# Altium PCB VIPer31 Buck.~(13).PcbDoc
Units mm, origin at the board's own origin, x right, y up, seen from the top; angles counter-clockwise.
Board outline 152.4 x 101.6 mm, 2 copper layers (Top Layer, Bottom Layer); 37 components, 16 nets, 72 pads, 0 vias.
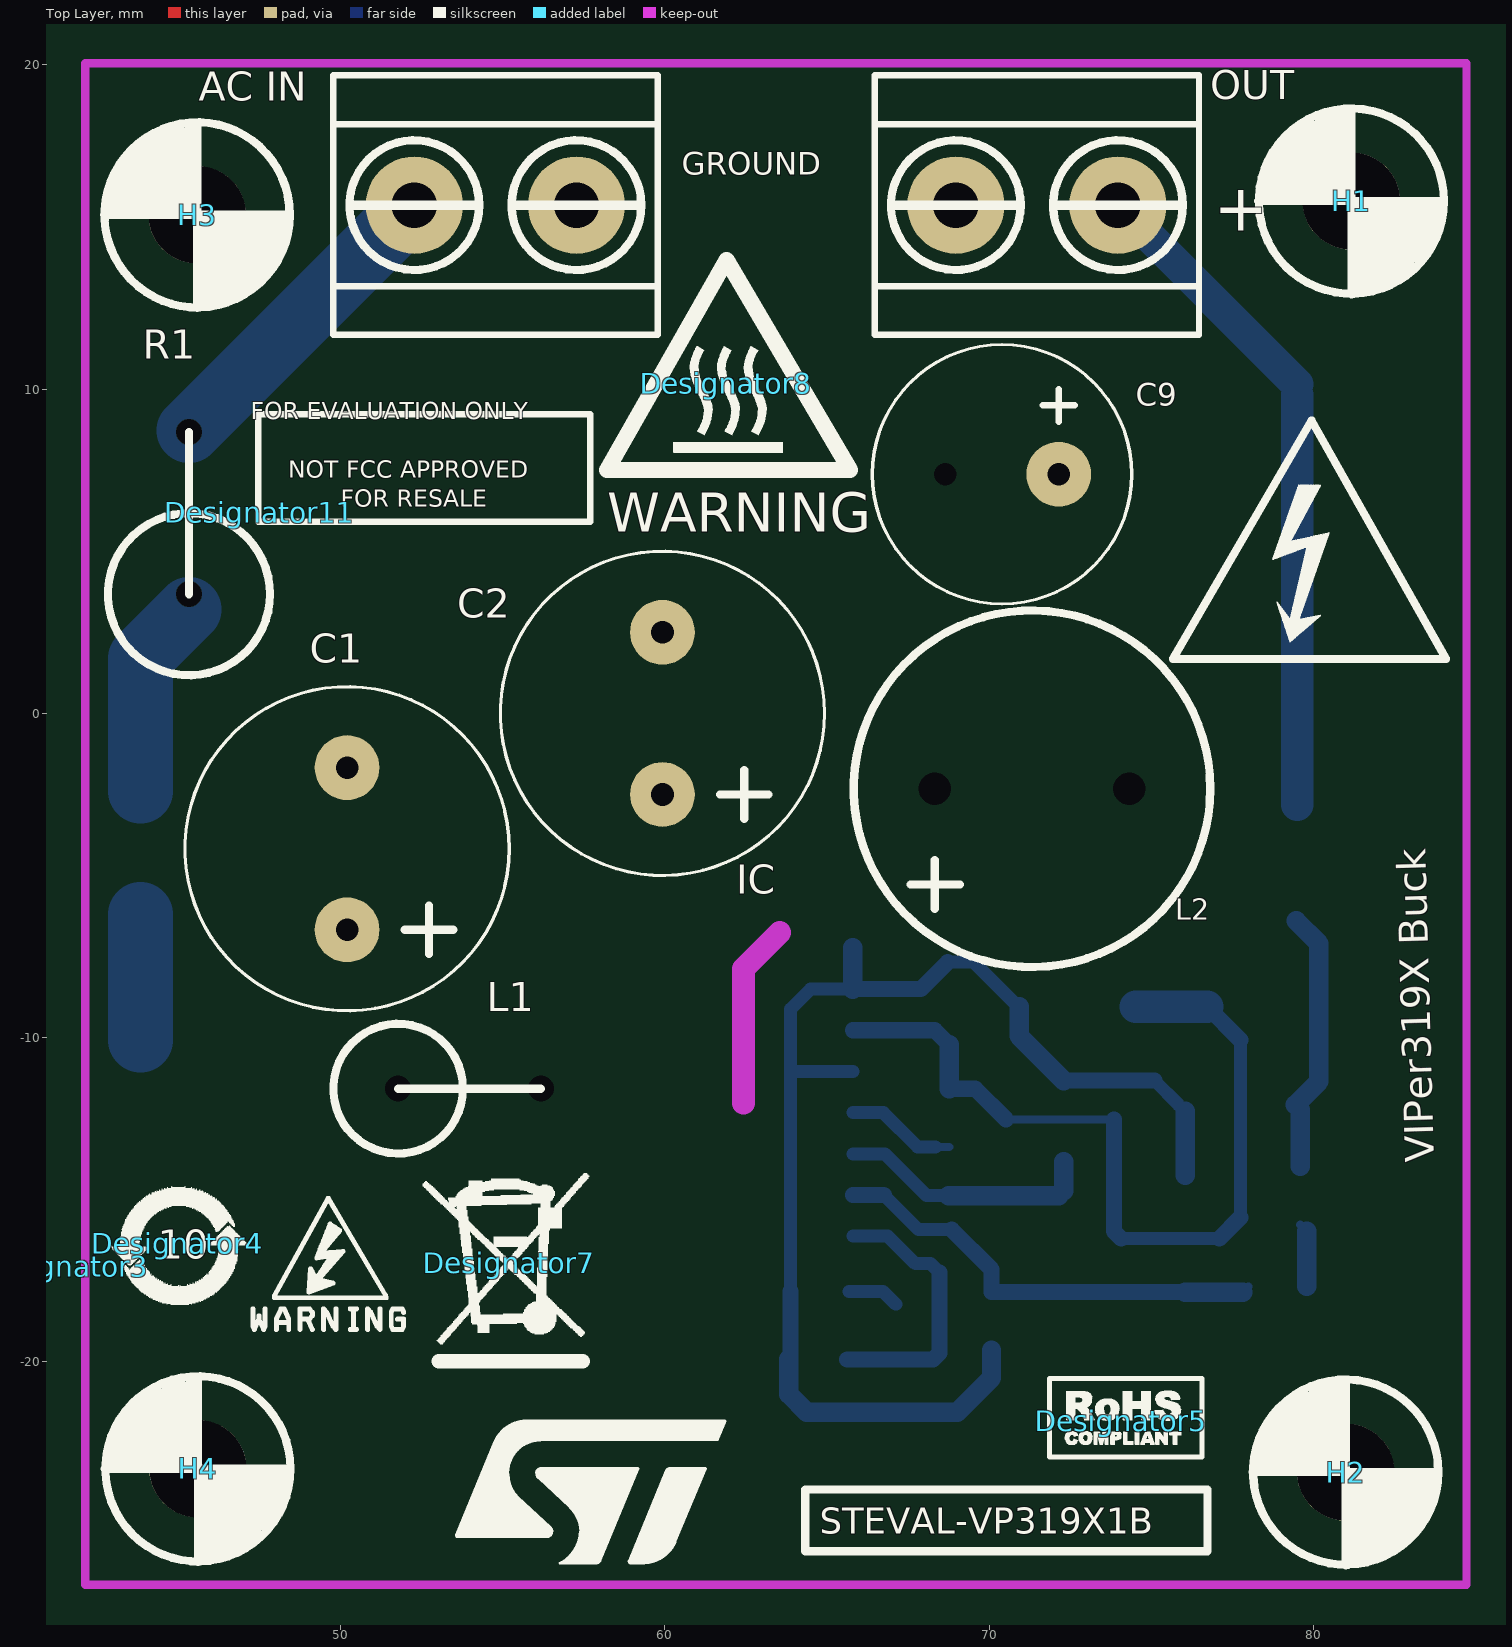
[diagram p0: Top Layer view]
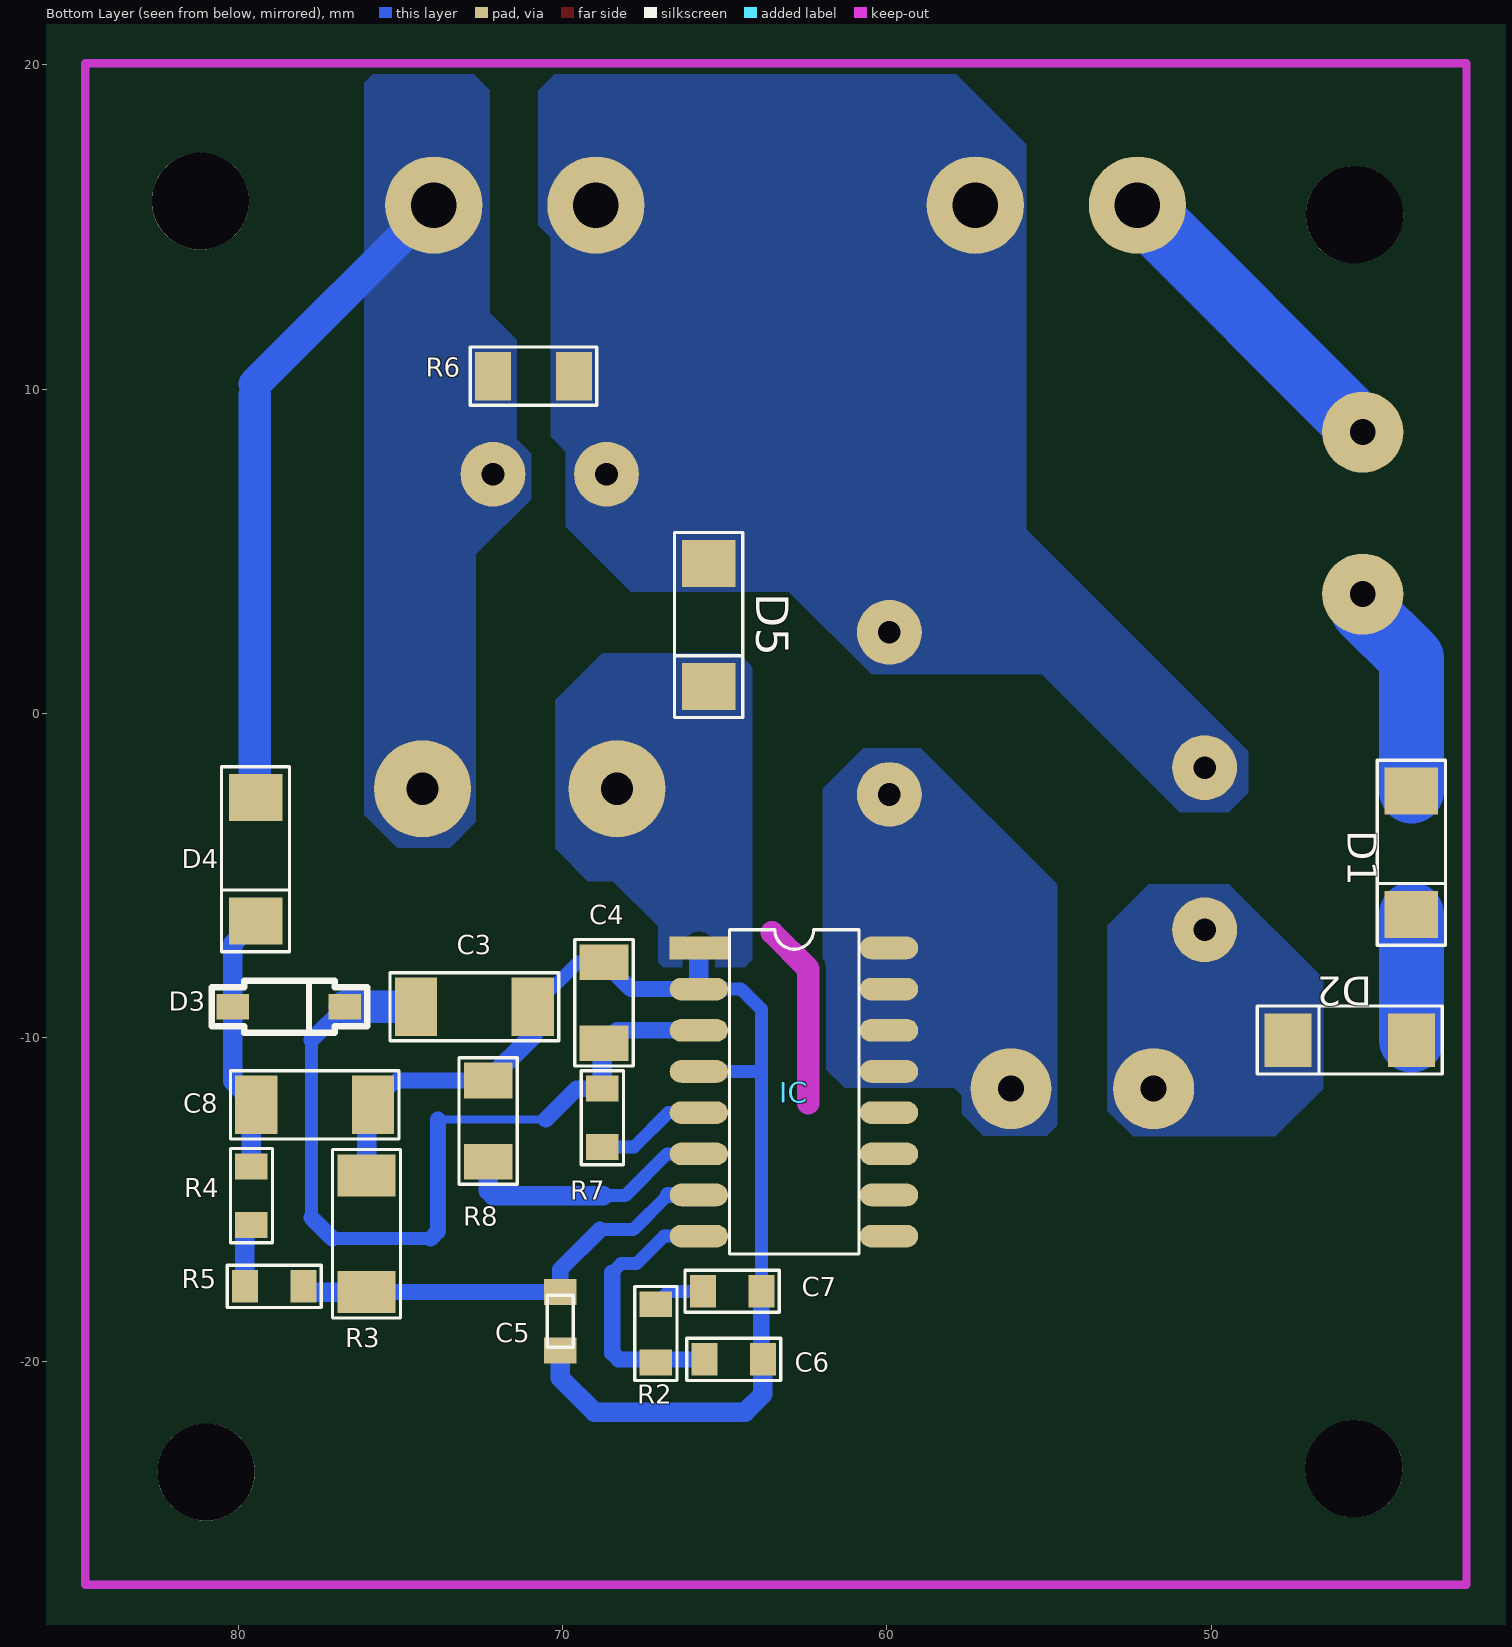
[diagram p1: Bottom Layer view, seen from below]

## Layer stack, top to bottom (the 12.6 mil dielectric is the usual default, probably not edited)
Top Solder: solder mask 0.0102, Solder Resist, Dk 3.5
Top Layer: signal copper 0.0356
Dielectric 1: dielectric 0.32, FR-4, Dk 4.8
Bottom Layer: signal copper 0.0356
Bottom Solder: solder mask 0.0102, Solder Resist, Dk 3.5

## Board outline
-0.1,-51.05 152.3,-51.05 152.3,50.55 -0.1,50.55

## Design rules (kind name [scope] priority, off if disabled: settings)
Clearance Clearance_1 [All] p1: gap=0.2 ignorepadtopadclearanceinfootprint=FALSE except(0: Arc-Hole Track-Hole SMDPad-Hole THPad-Hole Via-Hole Fill-Hole Poly-Hole Region-Hole Text-Hole)
Clearance [All] p2: gap=0.254 ignorepadtopadclearanceinfootprint=FALSE except(0: Arc-Poly Arc-Hole Track-Poly Track-Region Track-Hole SMDPad-Poly SMDPad-Hole THPad-Poly THPad-Hole Via-Poly Via-Hole Fill-Poly Fill-Hole Poly-Poly Poly-Hole Region-Hole Text-Hole)
PolygonConnect [All] p1: connectstyle=Direct reliefconductorwidth=0.254 reliefentries=4 polygonreliefangle="90 Angle" airgapwidth=0.254
RoutingVias [All] p1: holewidth=0.711 width=1.27 viastyle="Through Hole" minholewidth=0.711 minwidth=1.27 maxholewidth=0.711 maxwidth=1.27
SolderMaskExpansion [All] p1: expansion=0.102
Width [All] p1: maxlimit=2 minlimit=0.254 preferedwidth=0.254 minimp=50.000000 maximp=50.000000 favimp=50.000000
30 further rules are at their usual default settings.

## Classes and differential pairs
component class VIPer31_buck: "AC IN" C1 C2 C3 C4 C5 C6 C7 C8 C9 D1 D2 D3 D4 D5 H1 H2 H3 H4 IC L1 L2 OUT R1 R2 R3 R4 R5 R6 R7 R8 Rbl VR1

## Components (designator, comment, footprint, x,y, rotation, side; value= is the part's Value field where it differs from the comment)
"AC IN" "input connector" SM.2VITE 57.275,15.675 r180 top (schematic designator IN)
C1 "22 uF 400 Vcc" CAPOL-5X10 50.2,-6.675 r90 top value="68 uF +/-20%, 400 Vcc, +105°C"
C2 "22 uF 400 Vcc" CAPOL-5X10 59.925,-2.5 r90 top value="68 uF +/-20%, 400 Vcc, +105°C"
C3 "4.7uF 50V" R-1206-B2 74.525,-9.05 r180 top value="1 nF 630 Vdc"
C4 "100pF" R-0805-B2 68.725,-10.175 r90 top value="100 pF +/-5%, 250 Vdc"
C5 "n.c." R-0603-B 70.075,-19.65 r90 top value=100pF
C6 "tbd" R-0603-B2 65.625,-19.925 r180 top value="1 nF +/-5%, 200 Vdc"
C7 "tbd" R-0603-B2 65.675,-17.825 r180 top
C8 "220 nF" R-1206-B2 79.45,-12.075 r180 top value="100nF ±10%, 25 Vcc"
C9 "680 uF, 25 Vcc" CAPOL-3.5X8 72.15,7.375 r180 top value="470 uF +/-20%, 35 Vcc, +105°C"
D1 "MRA4007" SMA-2 43.825,-2.4 r90 top
D2 "MRA4007" SMA-2 43.825,-10.075 r180 top
D3 "BAT46ZFILM" SOD-123 80.175,-9.05 r0 top value=MRA4007T3G
D4 "STTH1L06" SMA-2 79.475,-2.6 r90 top value="1 A, 150 V"
D5 "STTH1L06" SMA-2 65.5,4.625 r90 top value="Schottky diode, 10A, 200 V"
Designator3 "Comment" High-Voltage-Logo-5mm 41.425,-17.05 r0 top
Designator4 "Comment" "RoHS-CH-Logo 10-4mm" 44.975,-16.35 r0 top
Designator5 "Comment" RoHS-EU-Logo-4.5mm 74.075,-21.825 r0 top
Designator7 "Comment" WASTE_5mm 55.2,-16.95 r0 top
Designator8 "Comment" "HOT SURFACE-logo-8mm" 61.9,10.175 r0 top
Designator11 "Comment" ADVISE_small 47.5,6.2 r0 top
H1 "HOLE" FORO 81.175,15.8 r0 top
H2 "HOLE" FORO 81,-23.4 r0 top
H3 "HOLE" FORO 45.575,15.375 r0 top
H4 "HOLE" FORO 45.6,-23.3 r0 top
IC "VIPER31_SO16" SO-16N_2 65.8,-7.235 r270 top
L1 "1mH" 1W-VER 51.775,-11.575 r0 top value="3.3UH 3.23A 33 MOHM"
L2 "270uH" CAPOL-6X11 68.325,-2.325 r0 top value="3.3UH 3.23A 33 MOHM"
OUT "output connector" SM.2VITE 73.975,15.675 r180 top
R1 "10 Ohm" 2W-VER 45.325,3.675 r90 top
R2 "tbd" R-0603-B2 67.125,-18.225 r270 top
R3 "22k" R-1206-B2 76.05,-14.25 r270 top value="0 Ohm, 0.25W"
R4 "22k" R-0603-B2 79.6,-15.775 r90 top
R5 "56k" R-0603-B2 79.8,-17.675 r180 top
R6 "5.6 kOhm" R-0805-B2 69.65,10.4 r0 top value="1MOhm +/-5%"
R7 "0" R-0603-B2 68.775,-11.575 r270 top
R8 "Res1" R-0805-B2 72.3,-11.325 r270 top value=0

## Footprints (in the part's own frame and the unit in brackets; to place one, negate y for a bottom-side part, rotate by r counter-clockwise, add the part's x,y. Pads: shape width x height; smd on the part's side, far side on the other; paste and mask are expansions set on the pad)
1W-VER [mm]
  round 0 / inner round 0 / far side round 2.5 hole 0.8: 1(0,0) 2(4.4,0)
  silkscreen extent -2,-2 4.4,2
2W-VER [mm]
  round 0 / inner round 0 / far side round 2.5 hole 0.8: 1(0,0) 2(5,0)
  silkscreen extent -2.5,-2.5 5,2.5
ADVISE_small [mm]
  silkscreen extent -0.04,-0.29 10.2,3.02
CAPOL-3.5X8 [mm]
  round 2 hole 0.7: 1(0,0)
  round 0 / inner round 0 / far side round 2 hole 0.7: 2(3.5,0)
  silkscreen extent -2.25,-4 5.75,4
CAPOL-5X10 [mm]
  round 2 hole 0.7: 1(0,0) 2(5,0)
  silkscreen extent -2.5,-5 7.5,5
CAPOL-6X11 [mm]
  round 0 / inner round 0 / far side round 3 hole 1: 1(0,0) 2(6,0)
  silkscreen extent -2.5,-5.5 8.5,5.5
FORO [mm]
  round 3 hole 3: 1(0,0)
  silkscreen extent -2.88,-2.88 2.86,2.86
High-Voltage-Logo-5mm [mm]
  silkscreen extent 5.83,-1.99 10.55,2.13
"HOT SURFACE-logo-8mm" [mm]
  silkscreen extent -3.68,-2.67 3.81,3.81
R-0603-B [mm]
  rect 0.8x1 smd far side: 1(0,0) 2(1.8,0)
R-0603-B2 [mm]
  rect 0.8x1 smd far side: 1(0,0) 2(1.8,0)
R-0805-B2 [mm]
  rect 1.1x1.5 smd far side: 1(0,0) 2(2.5,0)
R-1206-B2 [mm]
  rect 1.3x1.8 smd far side: 1(0,0) 2(3.6,0)
"RoHS-CH-Logo 10-4mm" [mm]
  silkscreen extent -2.05,-1.88 2.14,1.74
RoHS-EU-Logo-4.5mm [mm]
  silkscreen extent -2.21,-1.11 2.5,1.31
SM.2VITE [mm]
  round 3 hole 1.4: 1(0,0) 2(5,0)
  silkscreen extent -2.5,-4 7.5,4
SMA-2 [mm]
  rect 1.45x1.65 smd far side: 1(0,0) 2(-3.8,0)
SO-16N_2 [mm]
  rect 0.7x1.8 smd far side: 1(0,0)
  oval 0.7x1.8 smd far side: 2(1.27,0) 3(2.54,0) 4(3.81,0) 5(5.08,0) 6(6.35,0) 7(7.62,0) 8(8.89,0) 9(8.89,-5.864) 10(7.62,-5.864) 11(6.35,-5.864) 12(5.08,-5.864) 13(3.81,-5.864) 14(2.54,-5.864) 15(1.27,-5.864) 16(0,-5.864)
SOD-123 [mm]
  rect 1x0.8 smd far side: 1(0,0) 2(-3.45,0)
WASTE_5mm [mm]
  silkscreen extent -2.67,-3.03 2.46,2.77

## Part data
"AC IN" OUT: library part M.2VITE, "Morsetti"
C1 C2: library part "Cap Pol1", "Polarized Capacitor (Radial)", Package="TH D{}18 mm, H{}25 mm, P{}7.5 mm", Part number=400BXC68MEFC18X25
C3: library part CAP, "1 nF 630 V multi layer capacitor", Package="SMD 1206", Part number=C3216C0G2J102J085AA
C4: library part CAP, "100 pF 250 Vdc multi layer capacitor", Package="SMD 0603", Part number=CGA3E3C0G2E101J080AA
C5: library part Cap, "Capacitor"
C6: library part CAP, "1 nF 200 Vdc multi layer capacitor", Package="SMD 0603", Part number=C0603C102J2GACAUTO
C7: library part CAP, "NC", Package="SMD 0603"
C8: library part CAP, "100nF ±10%, 25 Vcc, MLCC", Package="SMD 0603", Part number=C0603C104K3RACTU
C9: library part "Cap Pol1", "470 uF +/-20%, 35 Vcc, +105°C", Package="TH D{}10 mm, H{}12.5 mm, P{}5 mm", Part number=25ZLH470MEFC10X12.5
D1 D2: library part "Diode 1N4007", "1 Amp General Purpose Rectifier"
D3: library part Diode, "Silicon Diode, 1 A, 1000 V", Part number=MRA4007T3G
D4: library part Diode, "small signal diode", Part number=STPS1150A
D5: library part Diode, "Schottky diode, 10A, 200 V", Part number=STPS2200UF
IC: "Integrato"
L1 L2: library part Inductor, "FIXED IND 3.3UH 3.23A 33 MOHM", Package="Lu x La: 0,157 x 0,157\" (4,00 x 4,00 mm)", Part number=74404043033A
R1: library part Res2, Package="TH 9 mm X 4 mm , P 5mm", Part number=NTPA7100LBMB0
R2 R4 R5: library part Res1, "Not connected", Package="SMD 0603"
R3: library part Res1, "0O, 0.25W, pkg 0603, serie CRCW", Package="SMD 0603", Part number=CRCW06030000Z0EAHP
R6: library part Res1, "6.8 kOhm +/-1% 0.125W, 0805 Panasonic", Package="SMD 1206", Part number=ERJP08J105V
R7: library part Res1, "Resistor"
R8: "Resistor"

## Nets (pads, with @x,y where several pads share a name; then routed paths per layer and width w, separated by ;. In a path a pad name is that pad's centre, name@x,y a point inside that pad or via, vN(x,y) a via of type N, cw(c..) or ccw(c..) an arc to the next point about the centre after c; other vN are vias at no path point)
GND: "AC IN.1" C1.2 C2.2 C9.2 D5.1 OUT.2 R6.1
NetC1_1: C1.1 D2.2 L1.1
NetC2_1: C2.1 IC.13 IC.14 IC.15 IC.16 L1.2
NetC3_1: C3.1 C4.1 D3.2 IC.3 R7.1 | length 26.8
  Bottom Layer w0.254: C4.1 C4.1@68.775,-10.225 ; 70.525,-12.525 73.85,-12.525
  Bottom Layer w0.4: 74.075,-16.2 77.1,-16.2 ; 77.75,-15.55 77.75,-10.075
  Bottom Layer w0.5: IC.3 68.325,-9.775 C4.1 ; R7.1 69.575,-11.575 70.525,-12.525 ; 73.85,-12.525 73.85,-15.975 74.075,-16.2 ; D3.2 77.75,-10.075 ; 77.1,-16.2 77.75,-15.55
  Bottom Layer w0.6: R7.1 C4.1@68.775,-10.225
  Bottom Layer w1: C3.1 D3.2
NetC3_2: C3.2 C4.2 C5.1 C6.2 C7.2 C8.2 D5.2 IC.1 IC.2 IC.4 L2.1 R3.1 R8.1 | length 40
  Bottom Layer w0.254: C6.2 C6.2@63.875,-19.875 ; 63.875,-11.05 63.88,-11.045 ; C3.2@70.9,-9.05 C3.2 ; C8.2 C8.2@76.05,-12.275
  Bottom Layer w0.4: C7.2@63.875,-17.8 63.875,-11.05 63.875,-9.125 64.495,-8.505 IC.2 ; 63.88,-11.045 IC.4 ; C4.2 69.525,-7.675 C3.2@70.9,-9.05 ; 75.1,-11.325 C8.2
  Bottom Layer w0.5: C6.2@63.875,-19.875 C7.2 ; IC.2 67.895,-8.505 C4.2 ; R8.1 75.1,-11.325
  Bottom Layer w0.6: C6.2 63.825,-21 64.375,-21.55 69.025,-21.55 70.075,-20.5 C5.1 ; IC.2 IC.1 ; C3.2 70.925,-9.95 R8.1 ; R3.1 C8.2@76.05,-12.275
NetC5_2: C5.2 IC.7 R3.2 R5.2 | length 13.9
  Bottom Layer w0.254: R5.2@77.825,-17.85 R5.2
  Bottom Layer w0.4: 66.755,-14.855 67.825,-15.925 68.85,-15.925
  Bottom Layer w0.5: IC.7 66.755,-14.855 ; 68.85,-15.925 70.075,-17.15 C5.2 R3.2
  Bottom Layer w0.6: R3.2 R5.2@77.825,-17.85
NetC6_1: C6.1 IC.8 R2.2 | length 8.5
  Bottom Layer w0.4: IC.8 66.875,-16.125 67.725,-16.975 68.2,-16.975 68.475,-17.25
  Bottom Layer w0.5: C6.1 68.275,-19.925 68.475,-19.725 68.475,-17.25
NetC7_1: C7.1 R2.1 | length 1.6
  Bottom Layer w0.4: C7.1 66.725,-17.825 R2.1
NetC8_1: C8.1 D3.1 D4.2 R4.2 | length 8.2
  Bottom Layer w0.254: C8.1 C8.1@79.6,-12.225
  Bottom Layer w0.6: C8.1 80.175,-11.35 D3.1 80.175,-7.1 D4.2 ; R4.2 C8.1@79.6,-12.225
NetC9_1: C9.1 D4.1 L2.2 OUT.1 R6.2 | length 20.8
  Bottom Layer w0.254: 79.5,9.825 79.5,10.15
  Bottom Layer w1: OUT.1 79.5,10.15 ; D4.1@79.5,-2.825 79.5,9.825
NetD1_1: D1.1 R1.1 | length 6.2
  Bottom Layer w2: D1.1 43.825,1.7 R1.1@45.325,3.2
NetD1_2: D1.2 D2.1 | length 3.9
  Bottom Layer w2: D2.1 D1.2
NetIC_5: IC.5 R7.2 | length 3.4
  Bottom Layer w0.254: R7.2@68.35,-13.375 R7.2
  Bottom Layer w0.4: IC.5 66.74,-12.315 67.8,-13.375 R7.2@68.35,-13.375
NetIC_6: IC.6 R8.2 | length 8
  Bottom Layer w0.254: 72.15,-14.875 72.3,-14.725
  Bottom Layer w0.4: IC.6 66.785,-13.585 68.075,-14.875 68.75,-14.875
  Bottom Layer w0.6: 68.75,-14.875 72.15,-14.875 ; 72.3,-14.725 R8.2
NetIN_2: "AC IN.2" R1.2 | length 9.8
  Bottom Layer w2: R1.2@45.325,8.725 52.275,15.675
NetR4_1: R4.1 R5.1 | length 2
  Bottom Layer w0.254: R4.1 R4.1@79.8,-15.975
  Bottom Layer w0.6: R5.1 R4.1@79.8,-15.975
pads on no net: H1.1 H2.1 H3.1 H4.1 IC.9 IC.10 IC.11 IC.12

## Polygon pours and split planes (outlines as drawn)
GND on Bottom Layer "GND" (solid, remove dead copper, pour order 44): 67.9,3.75 69.9,5.75 69.9,8.075 70.375,8.55 70.375,14.675 70.75,15.05 70.75,19.2 70.275,19.675 70.275,19.775 57.925,19.775 55.7,17.55 55.7,5.675 48.85,-1.175 48.85,-2.45 49.45,-3.05 50.975,-3.05 55.225,1.2 60.475,1.2 63.025,3.75
NetC2_1 on Bottom Layer "NetC2_1" (solid, remove dead copper, pour order 40): 54.75,-12.7 55.075,-13.025 57.025,-13.025 57.7,-12.35 57.7,-11.775 57.925,-11.55 61.3,-11.55 61.975,-10.875 61.975,-2.325 60.725,-1.075 58.95,-1.075 54.75,-5.275
NetC1_1 on Bottom Layer "NetC1_1" (solid, remove dead copper, pour order 38): 46.55,-11.575 48.025,-13.05 52.4,-13.05 53.2,-12.25 53.2,-6.55 51.925,-5.275 49.45,-5.275 46.55,-8.175
NetC9_1 on Bottom Layer "NetC9_1" (solid, remove dead copper, pour order 34): 72.25,12.35 71.425,11.525 71.425,8.45 70.975,8 70.975,6.6 72.675,4.9 72.675,-3.35 73.475,-4.15 75.1,-4.15 76.125,-3.125 76.125,19.45 75.8,19.775 72.8,19.775 72.25,19.225
NetC3_2 on Bottom Layer "Bottom Layer-No Net" (solid, remove dead copper, pour order 12): 64.15,0.725 64.15,-6.725 64.15,-7.6 64.35,-7.8 64.375,-7.825 66.375,-7.825 66.9,-7.825 67.05,-7.675 67.05,-7.425 67.05,-6.575 67.075,-6.55 68.45,-5.175 68.825,-5.175 69.225,-5.175 70.175,-4.225 70.225,-4.175 70.225,-3.025 70.225,0.4 68.775,1.85 64.75,1.85 64.575,1.85 64.25,1.525 64.15,1.425 64.15,0.75

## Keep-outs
Keep-Out Layer:
  lines w0.254: 42.125,-26.875 42.125,20.05 84.725,20.05 84.725,-26.875 42.125,-26.875
  lines w0.7: 62.425,-12.025 62.425,-7.875 63.542,-6.758

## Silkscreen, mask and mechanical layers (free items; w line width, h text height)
Top Overlay:
  drawing of 6721 lines, arcs and shapes, not listed
  text "GROUND" at 60.525,16.375 h1.2
  text "+" at 76.925,14.4 h2.5
  text "VIPer319X Buck" at 84.025,-13.825 h1.52 r91.6
  text "STEVAL-VP319X1B" at 64.779,-25.305 h0.8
